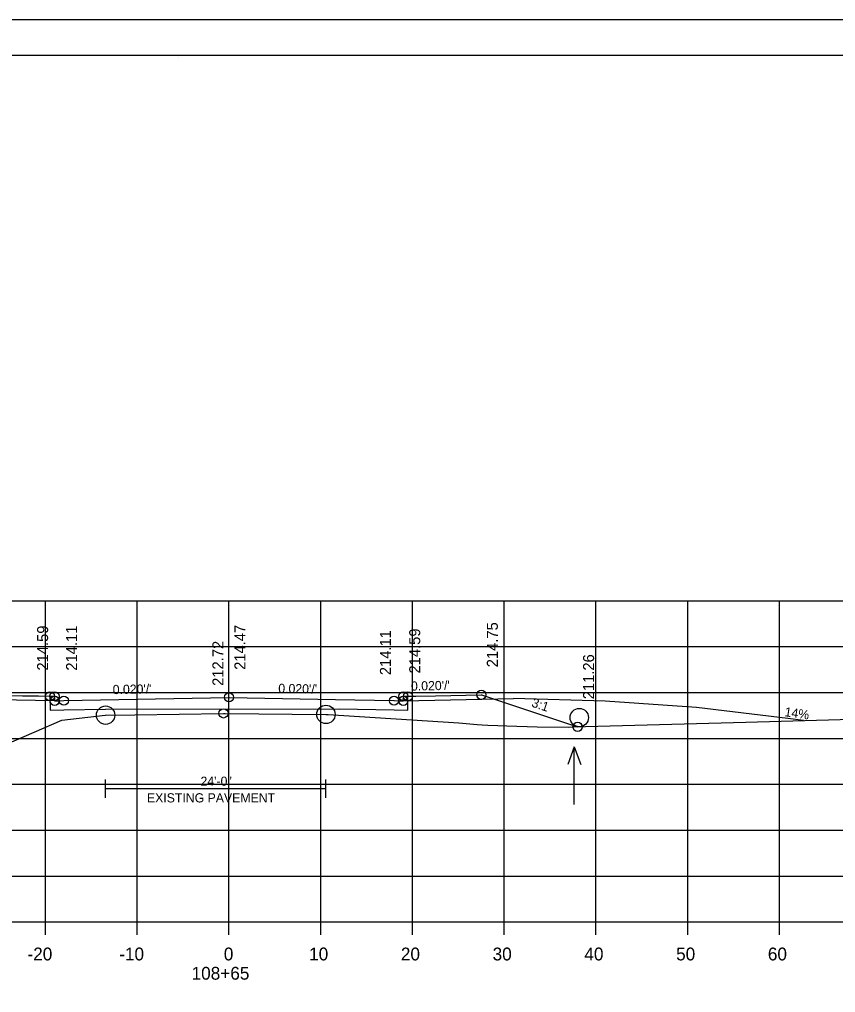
# Model space of a CAD drawing. Extents: x 1368968 to 1369915, y 377395 to 380381.
# Drawn here: x 1369115.3 to 1369204.2, y 379435 to 379541.1 of the extents above; entities that cross this region are included whole.
import ezdxf

# ---------------------------------------------------------------- set-up
doc = ezdxf.new("R2010")
doc.units = 0
for name, color, linetype in [('S_BORDER_NO_PLOT', 7, 'Continuous'), ('S_BREAKLINE_ANNOT', 7, 'Continuous'), ('S_BRIDGE', 7, 'Continuous'), ('S_BRIDGE_ANNOT', 7, 'Continuous'), ('S_CROSS_DRAIN', 7, 'Continuous'), ('S_CTL_TABLE', 7, 'Continuous'), ('S_CURB_ANNOT', 7, 'Continuous'), ('S_DITCHLINE_ANNOT', 7, 'Continuous'), ('S_DROP_INLET', 7, 'Continuous'), ('S_EXIST_ROW_ANNOT', 7, 'Continuous'), ('S_EXISTING_ALIGNMENT', 7, 'Continuous'), ('S_EXISTING_ALIGNMENT_ANNOT', 7, 'Continuous'), ('S_FENCE', 7, 'Continuous')]:
    doc.layers.add(name, color=color, linetype=linetype)

msp = doc.modelspace()

# ---------------------------------------------------------------- linework, layer by layer
at = {"layer": 'S_BORDER_NO_PLOT'}
msp.add_lwpolyline([(1369118.62, 379467.31), (1369118.63, 379465.8), (1369120.13, 379465.83), (1369124.68, 379465.92), (1369150.13, 379465.95), (1369156.13, 379465.83), (1369157.63, 379465.8), (1369157.64, 379467.31)], dxfattribs=at)
at = {"layer": 'S_BREAKLINE_ANNOT'}
for p, q in [((1368998.13, 379442.72), (1369278.13, 379442.72)), ((1369118.13, 379441.32), (1369118.13, 379442.72)), ((1369128.13, 379441.32), (1369128.13, 379442.72)), ((1369138.13, 379441.32), (1369138.13, 379442.72)), ((1369148.13, 379441.32), (1369148.13, 379442.72)), ((1369158.13, 379441.32), (1369158.13, 379442.72)), ((1369168.13, 379441.32), (1369168.13, 379442.72)), ((1369178.13, 379441.32), (1369178.13, 379442.72)), ((1369188.13, 379441.32), (1369188.13, 379442.72)), ((1369198.13, 379441.32), (1369198.13, 379442.72))]:
    msp.add_line(p, q, dxfattribs=at)
at = {"layer": 'S_BRIDGE_ANNOT'}
for p, q in [((1368980.13, 379537.18), (1369296.31, 379537.18)), ((1369132.65, 379536.92), (1369132.65, 379536.92)), ((1369132.65, 379536.92), (1369132.65, 379536.92))]:
    msp.add_line(p, q, dxfattribs=at)
at = {"layer": 'S_CROSS_DRAIN'}
for p, q in [((1369119.13, 379466.81), (1369107.14, 379467.05)), ((1369157.13, 379466.81), (1369169.13, 379467.05)), ((1369179.13, 379466.79), (1369169.13, 379467.05)), ((1369189.11, 379466.07), (1369179.13, 379466.79)), ((1369199.03, 379464.9), (1369189.11, 379466.07)), ((1369200.76, 379464.66), (1369199.03, 379464.9)), ((1369124.68, 379457.25), (1369148.7, 379457.25))]:
    msp.add_line(p, q, dxfattribs=at)
at = {"layer": 'S_CTL_TABLE'}
msp.add_lwpolyline([(1369112.76, 379461.62), (1369116.91, 379463.38), (1369119.93, 379464.7), (1369124.63, 379465.25), (1369124.68, 379465.25), (1369127.87, 379465.3), (1369137.54, 379465.44), (1369137.7, 379465.44), (1369148.7, 379465.33), (1369148.76, 379465.33), (1369148.78, 379465.33), (1369148.79, 379465.33), (1369148.8, 379465.32), (1369148.83, 379465.32), (1369148.87, 379465.32), (1369148.9, 379465.32), (1369148.95, 379465.31), (1369163.2, 379464.4), (1369163.98, 379464.34), (1369165.2, 379464.24), (1369165.72, 379464.21), (1369166.36, 379464.17), (1369167.44, 379464.11), (1369168.42, 379464.08), (1369171.73, 379463.96), (1369175.11, 379463.93), (1369175.66, 379463.96), (1369194.47, 379464.48), (1369208.59, 379464.88)], dxfattribs=at)
at = {"layer": 'S_CURB_ANNOT'}
msp.add_lwpolyline([(1369110.63, 379467.47), (1369115.62, 379467.37), (1369115.63, 379467.37), (1369117.38, 379467.34), (1369118.62, 379467.31), (1369118.62, 379467.31), (1369119.12, 379467.31), (1369119.13, 379466.81), (1369119.73, 379466.82), (1369120.13, 379466.83), (1369120.15, 379466.83), (1369138.13, 379467.19), (1369138.18, 379467.19), (1369149.73, 379466.96), (1369156.09, 379466.83), (1369156.13, 379466.83), (1369156.6, 379466.82), (1369157.13, 379466.81), (1369157.14, 379467.31), (1369157.64, 379467.31), (1369157.65, 379467.31), (1369158.51, 379467.33), (1369160.64, 379467.37), (1369160.64, 379467.37), (1369165.63, 379467.47), (1369165.64, 379467.47), (1369173.38, 379464.89), (1369176.13, 379463.98)], dxfattribs=at)
at = {"layer": 'S_DITCHLINE_ANNOT'}
for p, q in [((1368998.13, 379477.72), (1369278.13, 379477.72)), ((1369118.13, 379442.72), (1369118.13, 379477.72)), ((1369128.13, 379442.72), (1369128.13, 379477.72)), ((1369138.13, 379442.72), (1369138.13, 379477.72)), ((1369148.13, 379442.72), (1369148.13, 379477.72)), ((1369158.13, 379442.72), (1369158.13, 379477.72)), ((1369168.13, 379442.72), (1369168.13, 379477.72)), ((1369178.13, 379442.72), (1369178.13, 379477.72)), ((1369188.13, 379442.72), (1369188.13, 379477.72)), ((1369198.13, 379442.72), (1369198.13, 379477.72)), ((1368998.13, 379472.72), (1369278.13, 379472.72)), ((1368998.13, 379467.72), (1369278.13, 379467.72)), ((1368998.13, 379462.72), (1369278.13, 379462.72)), ((1368998.13, 379457.72), (1369278.13, 379457.72)), ((1368998.13, 379452.72), (1369278.13, 379452.72)), ((1368998.13, 379447.72), (1369278.13, 379447.72)), ((1368998.13, 379442.72), (1369278.13, 379442.72))]:
    msp.add_line(p, q, dxfattribs=at)
at = {"layer": 'S_DROP_INLET'}
msp.add_line((1368967.73, 379541.07), (1369301.07, 379541.07), dxfattribs=at)
for points in [[(1368967.73, 379541.07), (1369301.07, 379541.07), (1369301.07, 379327.74), (1368967.73, 379327.74)], [(1369214.05, 379537.18), (1369214.05, 379527.3), (1369249.79, 379527.3), (1369249.79, 379524.38), (1369272.99, 379524.38), (1369272.99, 379500.05), (1369296.31, 379500.05), (1369296.31, 379331.72), (1368980.13, 379331.72), (1368980.13, 379537.18)]]:
    msp.add_lwpolyline(points, close=True, dxfattribs=at)
for centre, radius in [((1369118.62, 379467.31), 0.5), ((1369119.12, 379467.31), 0.5), ((1369119.13, 379466.81), 0.5), ((1369120.13, 379466.83), 0.5), ((1369120.13, 379466.83), 0.5), ((1369138.13, 379467.19), 0.5), ((1369156.13, 379466.83), 0.5), ((1369156.13, 379466.83), 0.5), ((1369157.13, 379466.81), 0.5), ((1369157.14, 379467.31), 0.5), ((1369157.64, 379467.31), 0.5), ((1369165.64, 379467.47), 0.5), ((1369124.68, 379465.25), 1), ((1369148.7, 379465.33), 1), ((1369137.54, 379465.44), 0.5), ((1369176.13, 379463.98), 0.5)]:
    msp.add_circle(centre, radius, dxfattribs=at)
at = {"layer": 'S_EXIST_ROW_ANNOT'}
for p, q in [((1369124.68, 379456.25), (1369124.68, 379458.25)), ((1369148.7, 379456.25), (1369148.7, 379458.25))]:
    msp.add_line(p, q, dxfattribs=at)
msp.add_circle((1369176.32, 379464.99), 1, dxfattribs=at)
at = {"layer": 'S_EXISTING_ALIGNMENT'}
for p, q in [((1369175.77, 379461.8), (1369175.07, 379459.88)), ((1369175.77, 379455.52), (1369175.77, 379461.8)), ((1369175.77, 379461.8), (1369176.47, 379459.88))]:
    msp.add_line(p, q, dxfattribs=at)
at = {"layer": 'S_EXISTING_ALIGNMENT_ANNOT'}
msp.add_line((1369138.13, 379465.44), (1369138.13, 379475.44), dxfattribs=at)

# ---------------------------------------------------------------- texts
at = {"layer": 'S_BRIDGE'}
for s, p in [('-20', (1369116.17, 379438.52)), ('-10', (1369126.17, 379438.52)), ('0', (1369137.57, 379438.52)), ('10', (1369146.87, 379438.52)), ('20', (1369156.87, 379438.52)), ('30', (1369166.87, 379438.52)), ('40', (1369176.87, 379438.52)), ('50', (1369186.87, 379438.52)), ('60', (1369196.87, 379438.52)), ('108+65', (1369134.06, 379436.42))]:
    msp.add_text(s, height=1.4, dxfattribs=at).set_placement(p)
at = {"layer": 'S_CROSS_DRAIN'}
msp.add_text('14%', height=1, rotation=352.0304, dxfattribs=at).set_placement((1369198.65, 379465.14))
at = {"layer": 'S_EXIST_ROW_ANNOT'}
for s, p in [('24\'-0"', (1369135.03, 379457.55)), ('EXISTING PAVEMENT', (1369129.19, 379455.74))]:
    msp.add_text(s, height=1, dxfattribs=at).set_placement(p)
at = {"layer": 'S_EXISTING_ALIGNMENT_ANNOT'}
for s, p in [('214.59', (1369118.42, 379470.11)), ('214.11', (1369121.58, 379470.1)), ('214.47', (1369139.93, 379470.19)), ('214.59', (1369158.98, 379469.79)), ('214.75', (1369167.44, 379470.47)), ('214.11', (1369155.79, 379469.61)), ('212.72', (1369137.53, 379468.44)), ('211.26', (1369177.93, 379466.98))]:
    msp.add_text(s, height=1.2, rotation=90, dxfattribs=at).set_placement(p)
at = {"layer": 'S_FENCE'}
for s, rotation, p in [("0.020'/'", 1.1458, (1369125.47, 379467.54)), ("0.020'/'", 358.8542, (1369143.5, 379467.68)), ("0.020'/'", 1.1457, (1369157.98, 379467.92)), ('3:1', 341.5636, (1369171.04, 379466.2))]:
    msp.add_text(s, height=1, rotation=rotation, dxfattribs=at).set_placement(p)

doc.saveas('drawing.dxf')
